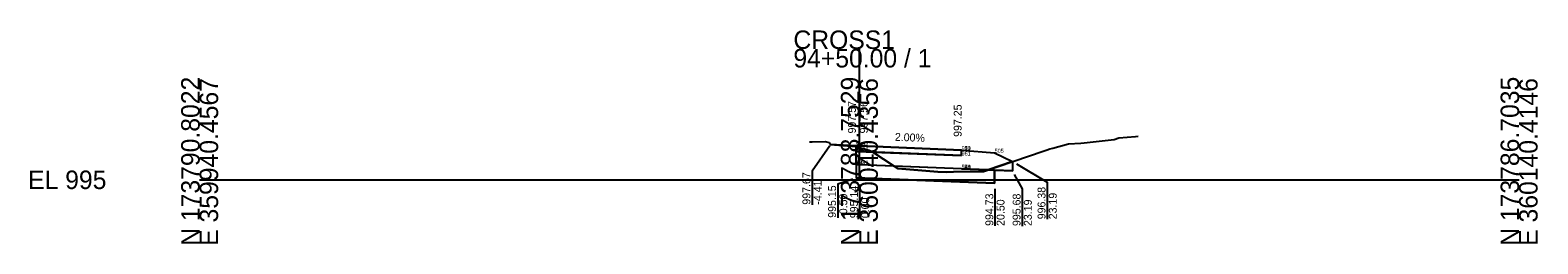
# Model space of a CAD drawing. Extents: x -26 to 1403, y -10 to 11027.
# Drawn here: x -25.7 to 202.8, y 9490.3 to 9522.7 of the extents above; entities that cross this region are included whole.
import ezdxf

# ---------------------------------------------------------------- set-up
doc = ezdxf.new("R2010")
doc.units = 0
for name, color, linetype in [('Default', 7, 'Continuous'), ('GSBWFILL', 7, 'Continuous'), ('GSCOLORFILL', 7, 'Continuous'), ('GSOUTLINE', 7, 'Continuous'), ('P_XS_EAR_CommonGrnd', 7, 'Continuous'), ('P_XS_Rock', 7, 'Continuous'), ('P_XS_Subgrade', 7, 'Continuous')]:
    doc.layers.add(name, color=color, linetype=linetype)

msp = doc.modelspace()

# ---------------------------------------------------------------- linework, layer by layer
at = {"layer": 'Default'}
for p, q in [((100, 9500), (100, 9519.81)), ((0, 9500), (100, 9500)), ((100, 9500), (200, 9500))]:
    msp.add_line(p, q, dxfattribs=at)
at = {"layer": 'GSBWFILL'}
for p, q in [((99.5, 9505.14), (95.59, 9505.35)), ((99.5, 9505.14), (100, 9505.12)), ((100, 9505.12), (115.5, 9504.5)), ((115.5, 9504.5), (120.5, 9504.1)), ((120.5, 9504.1), (123.19, 9502.76))]:
    msp.add_line(p, q, dxfattribs=at)
at = {"layer": 'GSCOLORFILL'}
for p, q in [((99.5, 9504.31), (99.5, 9505.14)), ((99.5, 9504.31), (100, 9504.29)), ((99.5, 9502.31), (99.5, 9504.31)), ((115.5, 9503.67), (100, 9504.29)), ((115.5, 9503.67), (115.5, 9504.5)), ((123.19, 9502.76), (123.19, 9501.36)), ((99.5, 9502.31), (100, 9502.29)), ((99.5, 9502.31), (99.5, 9500.31)), ((120.5, 9499.47), (99.5, 9500.31)), ((115.5, 9501.67), (100, 9502.29)), ((115.5, 9501.67), (123.19, 9501.36)), ((120.5, 9501.47), (120.5, 9499.47))]:
    msp.add_line(p, q, dxfattribs=at)
at = {"layer": 'P_XS_EAR_CommonGrnd'}
for points in [[(95.59, 9505.35), (98.84, 9505.1), (99.36, 9505.08), (99.5, 9505.04), (99.5, 9505.14)], [(115.5, 9503.67), (115.5, 9504.5), (100, 9505.12), (99.5, 9505.14), (99.5, 9505.04), (99.67, 9505), (100, 9504.91), (101.47, 9504.51), (101.98, 9504.25), (102.06, 9504.2)], [(102.06, 9504.2), (100, 9504.29), (99.5, 9504.31), (99.5, 9505.04), (99.67, 9505), (100, 9504.91), (101.47, 9504.51), (101.98, 9504.25)], [(105.28, 9502.07), (100, 9502.29), (99.5, 9502.31), (99.5, 9504.31), (100, 9504.29), (102.06, 9504.2)], [(115.5, 9503.67), (115.5, 9504.5), (120.5, 9504.1), (123.19, 9502.76), (119.52, 9501.51), (115.5, 9501.67), (105.28, 9502.07), (102.06, 9504.2)], [(119.52, 9501.51), (123.19, 9502.76), (123.19, 9501.36), (120.5, 9501.47)], [(105.28, 9502.07), (100, 9502.29), (99.5, 9502.31), (99.5, 9500.31), (120.5, 9499.47), (120.5, 9501.47), (119.52, 9501.51), (118.83, 9501.27), (114.25, 9501.19), (113.15, 9501.15), (111.91, 9501.21), (105.82, 9501.72)], [(115.5, 9501.67), (105.28, 9502.07), (105.82, 9501.72), (111.91, 9501.21), (113.15, 9501.15), (114.25, 9501.19), (118.83, 9501.27), (119.52, 9501.51)]]:
    msp.add_lwpolyline(points, close=True, dxfattribs=at)
at = {"layer": 'P_XS_Rock'}
for p, q in [((92.82, 9501.35), (95.51, 9505.18)), ((123.8, 9502.4), (128.46, 9499.63)), ((92.82, 9501.35), (92.82, 9496.23)), ((96.71, 9499.37), (99.01, 9500.14)), ((123.48, 9500.82), (124.68, 9498.61)), ((96.71, 9499.37), (96.71, 9494.25)), ((100.03, 9499.31), (100.03, 9494.18)), ((120.55, 9498.63), (120.55, 9493.02)), ((124.68, 9498.61), (124.68, 9492.99)), ((128.46, 9499.63), (128.46, 9494.02))]:
    msp.add_line(p, q, dxfattribs=at)
at = {"layer": 'P_XS_Subgrade'}
for p, q in [((92.45, 9505.77), (92.83, 9505.74)), ((92.83, 9505.74), (94.83, 9505.78)), ((94.83, 9505.78), (95.44, 9505.67)), ((95.44, 9505.67), (95.59, 9505.35)), ((95.59, 9505.35), (98.84, 9505.1)), ((98.84, 9505.1), (99.36, 9505.08)), ((99.36, 9505.08), (99.67, 9505)), ((99.67, 9505), (100, 9504.91)), ((100, 9504.91), (101.47, 9504.51)), ((128.47, 9504.53), (128.88, 9504.68)), ((128.88, 9504.68), (129.32, 9504.81)), ((129.32, 9504.81), (131.71, 9505.43)), ((131.71, 9505.43), (133.55, 9505.55)), ((133.55, 9505.55), (134.07, 9505.62)), ((134.07, 9505.62), (138.61, 9506.09)), ((138.61, 9506.09), (139.35, 9506.34)), ((139.35, 9506.34), (141.86, 9506.57)), ((141.86, 9506.57), (142.25, 9506.6)), ((101.47, 9504.51), (101.98, 9504.25)), ((101.98, 9504.25), (105.82, 9501.72)), ((118.83, 9501.27), (127.87, 9504.36)), ((127.87, 9504.36), (128.47, 9504.53)), ((105.82, 9501.72), (111.91, 9501.21)), ((111.91, 9501.21), (113.15, 9501.15)), ((113.15, 9501.15), (114.25, 9501.19)), ((114.25, 9501.19), (118.83, 9501.27))]:
    msp.add_line(p, q, dxfattribs=at)

# ---------------------------------------------------------------- texts
at = {"layer": 'Default'}
for s, p in [('CROSS1', (90, 9519.81)), ('94+50.00 / 1', (90, 9517.01)), ('EL 995', (-26, 9498.6))]:
    msp.add_text(s, height=2.8, dxfattribs=at).set_placement(p)
for s, p in [('N 173790.8022', (0, 9490)), ('E 359940.4567', (2.8, 9490)), ('N 173788.7529', (100, 9490)), ('E 360040.4356', (102.8, 9490)), ('N 173786.7035', (200, 9490)), ('E 360140.4146', (202.8, 9490))]:
    msp.add_text(s, height=2.8, rotation=90, dxfattribs=at).set_placement(p)
at = {"layer": 'GSOUTLINE'}
for s, p in [('951', (99.5, 9505.14)), ('9', (99.5, 9505.14)), ('900', (99.5, 9505.14)), ('961', (99.5, 9504.31)), ('952', (100, 9505.12)), ('952', (100, 9505.12)), ('962', (100, 9504.29)), ('962', (100, 9504.29)), ('951', (115.5, 9504.5)), ('9', (115.5, 9504.5)), ('900', (115.5, 9504.5)), ('910', (115.5, 9504.5)), ('505', (120.5, 9504.1)), ('971', (99.5, 9502.31)), ('998', (99.5, 9502.31)), ('972', (100, 9502.29)), ('972', (100, 9502.29)), ('961', (115.5, 9503.67)), ('540', (115.5, 9501.67)), ('971', (115.5, 9501.67)), ('998', (115.5, 9501.67))]:
    msp.add_text(s, height=0.6, dxfattribs=at).set_placement(p)
at = {"layer": 'P_XS_Rock'}
for s, rotation, p in [('997.57', 90, (99.47, 9507.02)), ('997.56', 90, (101.26, 9507.02)), ('997.25', 90, (115.5, 9506.5)), ('2.00%', 357.7094, (105.36, 9505.91)), ('997.67', 90, (92.57, 9496.23)), ('-4.41', 90, (94.27, 9496.23)), ('995.15', 90, (96.46, 9494.25)), ('-0.50', 90, (98.16, 9494.25)), ('995.14', 90, (99.78, 9494.19)), ('994.73', 90, (120.3, 9493.02)), ('995.68', 90, (124.43, 9493)), ('996.38', 90, (128.21, 9494.02)), ('23.19', 90, (129.91, 9494.02)), ('0.00', 90, (101.48, 9494.19)), ('20.50', 90, (122, 9493.02)), ('23.19', 90, (126.13, 9493))]:
    msp.add_text(s, height=1.2, rotation=rotation, dxfattribs=at).set_placement(p)

doc.saveas('drawing.dxf')
